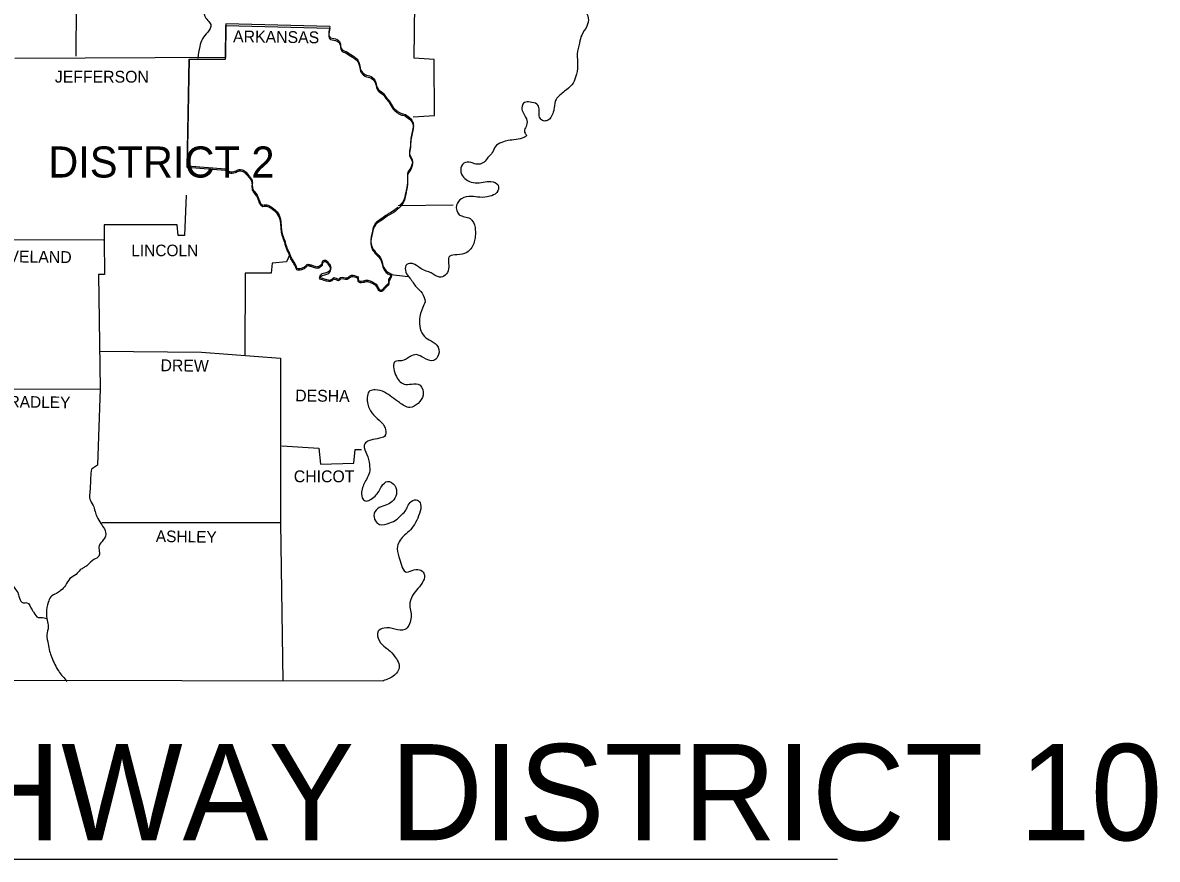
# Model space of a CAD drawing. Extents: x 191 to 3403, y 68 to 2102.
# Drawn here: x 2999.8 to 3403.5, y 1369.4 to 1667 of the extents above; entities that cross this region are included whole.
import ezdxf

# ---------------------------------------------------------------- set-up
doc = ezdxf.new("R2010")
doc.units = 0
for name, color, linetype in [('1', 7, 'Continuous'), ('2', 7, 'Continuous'), ('3', 7, 'Continuous')]:
    doc.layers.add(name, color=color, linetype=linetype)

msp = doc.modelspace()

# ---------------------------------------------------------------- linework, layer by layer
at = {"layer": '1'}
for p, q in [((3133.42, 1601.94), (3152.99, 1602.24)), ((2625.16, 1369.37), (3289.7, 1369.37))]:
    msp.add_line(p, q, dxfattribs=at)
for points in [[(3007.21, 1732.56), (3012.88, 1732.17), (3012.98, 1694.79), (3007.89, 1673.56), (3018.75, 1673.07), (3018.66, 1655.07)], [(3138.71, 1633.54), (3146.34, 1634.03), (3146.24, 1653.9), (3139.1, 1654.38), (3139.49, 1693.23), (3133.33, 1694.11), (3133.13, 1720.23), (3216.59, 1720.82)], [(3109.06, 1665.64), (3072.08, 1666.61), (3071.88, 1654.58), (2997.03, 1654.29)], [(3059.06, 1653.99), (3071.88, 1653.99), (3072.08, 1666.03), (3109.06, 1665.05)], [(3059.06, 1653.99), (3058.28, 1616.13), (3071.88, 1615.05)], [(3071.88, 1614.47), (3058.28, 1615.54), (3059.06, 1653.99)], [(3057.99, 1605.66), (3057.4, 1591.28), (3055.15, 1591.28), (3054.76, 1595.09), (3028.73, 1595.09), (3028.73, 1589.61)], [(2993.9, 1589.91), (3028.54, 1589.71)], [(3028.73, 1589.71), (3028.83, 1577.48), (3026.78, 1577.38), (3027.36, 1536.78)], [(3094.87, 1584.53), (3093.7, 1581.88), (3088.51, 1581.4), (3088.22, 1577.87), (3078.93, 1577.87), (3078.83, 1548.62)], [(3105.83, 1580.22), (3106.13, 1580.51), (3106.42, 1580.81), (3106.42, 1580.81)], [(3027.07, 1550.09), (3063.37, 1549.79), (3091.55, 1547.64)], [(3091.55, 1547.64), (3091.55, 1489.13), (3092.33, 1432.87)], [(2983.14, 1536.68), (3027.36, 1536.78)], [(3027.36, 1536.78), (3026.39, 1509.58), (3024.23, 1508.21)], [(3092.04, 1516.43), (3105.15, 1515.65), (3105.73, 1509.97), (3117.57, 1510.36), (3118.06, 1515.16), (3120.31, 1515.16)], [(2769.26, 1512.61), (2769.46, 1433.46), (3128.04, 1432.87)], [(3027.95, 1489.23), (3091.55, 1489.23)]]:
    msp.add_lwpolyline(points, dxfattribs=at)
for points in [[(3210.42, 1697.14), (3208.17, 1694.3), (3204.85, 1696.06), (3204.85, 1698.41), (3205.34, 1700.86), (3204.16, 1702.42), (3202.11, 1701.74), (3202.11, 1698.71), (3201.91, 1695.77), (3201.32, 1691.56), (3202.69, 1690.29), (3205.83, 1689.9), (3208.08, 1689.31), (3209.45, 1687.06), (3209.35, 1684.32), (3208.27, 1681.68), (3206.71, 1679.53), (3204.26, 1678.75), (3202.3, 1680.02), (3201.52, 1682.56), (3200.64, 1684.81), (3198.98, 1686.48), (3197.22, 1684.62), (3196.82, 1681.19), (3196.92, 1678.26), (3196.92, 1674.25), (3199.47, 1671.6), (3201.03, 1668.57), (3200.54, 1665.83), (3198.68, 1662.6), (3197.9, 1659.77), (3197.12, 1655.95), (3197.22, 1651.74), (3196.53, 1647.63), (3195.16, 1644.89), (3192.62, 1642.64), (3190.95, 1641.18), (3189.58, 1639.71), (3188.9, 1636.77), (3188.41, 1634.72), (3186.55, 1632.27), (3185.08, 1632.08), (3183.91, 1633.05), (3183.52, 1634.72), (3183.52, 1636.38), (3182.74, 1638.04), (3180.29, 1638.73), (3178.33, 1638.63), (3177.45, 1637.26), (3178.72, 1633.45), (3179.21, 1631), (3178.53, 1627.67), (3178.92, 1627.28), (3175.4, 1625.42), (3172.56, 1625.13), (3170.21, 1624.44), (3167.96, 1622.98), (3166.88, 1620.82), (3165.32, 1619.06), (3163.95, 1617.4), (3162.09, 1616.62), (3160.04, 1617.01), (3157.3, 1617.3), (3155.73, 1615.35), (3156.22, 1612.51), (3158.08, 1610.85), (3160.82, 1610.06), (3163.66, 1610.26), (3166.4, 1610.55), (3168.94, 1609.18), (3168.45, 1606.54), (3166, 1605.27), (3162.38, 1604.88), (3159.45, 1605.17), (3155.93, 1604.39), (3154.17, 1602.14), (3155.14, 1598.71), (3158.96, 1597.34), (3160.72, 1594.11), (3160.82, 1591.08), (3159.55, 1587.07), (3157.79, 1585.21), (3154.36, 1584.43), (3151.72, 1583.94), (3151.33, 1579.44), (3150.15, 1577.19), (3148.1, 1576.5), (3145.16, 1577.97), (3143.4, 1578.66), (3141.25, 1579.63), (3138.51, 1581.3), (3136.46, 1581), (3137.04, 1576.7), (3137.24, 1576.5), (3139.59, 1573.27), (3141.94, 1570.73), (3143.01, 1567.7)], [(3059.95, 1681.68), (3062.39, 1680.02), (3064.93, 1678.06), (3065.62, 1675.42), (3065.42, 1673.56), (3064.64, 1672), (3064.45, 1669.55), (3065.62, 1667.79), (3066.7, 1666.32), (3065.62, 1663.68), (3063.76, 1661.23), (3062.78, 1658.49), (3062.1, 1654.38)], [(3109.06, 1665.64), (3109.35, 1661.62), (3111.7, 1661.04), (3112.68, 1659.96), (3113.17, 1657.71), (3114.83, 1656.73), (3117.08, 1655.36), (3118.45, 1654.38), (3119.43, 1652.82), (3120.02, 1650.27), (3121.58, 1648.61), (3123.74, 1647.83), (3125.3, 1645.97), (3126.28, 1643.33), (3127.85, 1642.15), (3129.41, 1640.1), (3130.19, 1639.22), (3131.56, 1636.87), (3132.93, 1635.7), (3133.91, 1635.01), (3135.48, 1634.52), (3137.43, 1633.25), (3138.71, 1631.29), (3138.71, 1629.83), (3138.22, 1627.58), (3137.83, 1625.23), (3137.63, 1622.59), (3137.43, 1620.24), (3138.32, 1618.28), (3137.83, 1615.35), (3136.85, 1613.78), (3136.75, 1611.63), (3136.46, 1608.4), (3136.07, 1606.54), (3135.18, 1603.51), (3133.91, 1601.94)], [(3109.06, 1665.05), (3109.35, 1661.04), (3111.7, 1660.45), (3112.68, 1659.37), (3113.17, 1657.12), (3114.83, 1656.15), (3117.08, 1654.78), (3118.45, 1653.8), (3119.43, 1652.23), (3120.02, 1649.69), (3121.58, 1648.02), (3123.74, 1647.24), (3125.3, 1645.38), (3126.28, 1642.74), (3127.85, 1641.57), (3129.41, 1639.51), (3130.19, 1638.63), (3131.56, 1636.28), (3132.93, 1635.11), (3133.91, 1634.42), (3135.48, 1633.94), (3137.43, 1632.66), (3138.71, 1630.71), (3138.71, 1629.24), (3138.22, 1626.99), (3137.83, 1624.64), (3137.63, 1622), (3137.43, 1619.65), (3138.32, 1617.69), (3137.83, 1614.76), (3136.85, 1613.19), (3136.75, 1611.04), (3136.46, 1607.81), (3136.07, 1605.95), (3135.18, 1602.92), (3133.62, 1601.06)], [(3071.88, 1615.05), (3073.35, 1614.07), (3075.4, 1614.17), (3076.77, 1614.76), (3077.85, 1614.66), (3079.32, 1613.78), (3080.3, 1612.61), (3080.98, 1611.73), (3081.47, 1610.36), (3081.47, 1609.08), (3081.96, 1607.32), (3082.55, 1606.64), (3083.33, 1605.37), (3083.82, 1604.19), (3084.11, 1603.41), (3085.19, 1602.14), (3086.17, 1602.24), (3087.05, 1602.14), (3088.22, 1601.45), (3089.98, 1600.08), (3090.28, 1599.69), (3091.45, 1597.15), (3091.65, 1595.58), (3091.84, 1593.53), (3092.23, 1591.57), (3093.02, 1589.42), (3093.41, 1587.95), (3094.29, 1585.9), (3094.87, 1584.53), (3095.66, 1582.76), (3096.83, 1580.81), (3097.32, 1579.63), (3098.98, 1579.73), (3100.16, 1580.22), (3101.04, 1581), (3102.11, 1580.91), (3103.29, 1580.51), (3104.85, 1580.22), (3105.83, 1580.81), (3106.32, 1581.2), (3106.42, 1582.08), (3107.3, 1582.57), (3108.28, 1581.88), (3109.35, 1580.32), (3109.35, 1579.34), (3108.96, 1578.75), (3107.69, 1577.97), (3105.93, 1577.38), (3105.44, 1576.7), (3107.1, 1575.92), (3109.75, 1575.72), (3110.43, 1576.31), (3112.19, 1575.82), (3112.88, 1576.31), (3115.23, 1576.21), (3116.3, 1576.99), (3118.45, 1576.89), (3119.14, 1576.41), (3119.14, 1575.52), (3120.9, 1575.13), (3122.17, 1575.43), (3123.84, 1574.94), (3125.3, 1574.15), (3126.09, 1573.08), (3127.06, 1571.9), (3127.94, 1572.2), (3128.63, 1573.08), (3130.1, 1574.64), (3130.1, 1575.62), (3130.49, 1576.31), (3130.98, 1577.29)], [(3130.98, 1576.7), (3130.49, 1575.72), (3130.1, 1575.04), (3130.1, 1574.06), (3128.63, 1572.49), (3127.94, 1571.61), (3127.06, 1571.32), (3126.09, 1572.49), (3125.3, 1573.57), (3123.84, 1574.35), (3122.17, 1574.84), (3120.9, 1574.55), (3119.14, 1574.94), (3119.14, 1575.82), (3118.45, 1576.31), (3116.3, 1576.41), (3115.23, 1575.62), (3112.88, 1575.72), (3112.19, 1575.23), (3110.43, 1575.72), (3109.75, 1575.13), (3107.1, 1575.33), (3105.44, 1576.11), (3105.93, 1576.8), (3107.69, 1577.38), (3108.96, 1578.17), (3109.35, 1578.75), (3109.35, 1579.73), (3108.28, 1581.3), (3107.3, 1581.98), (3106.42, 1581.49), (3106.32, 1580.61), (3105.83, 1580.22), (3104.85, 1579.63), (3103.29, 1579.93), (3102.11, 1580.32), (3101.04, 1580.42), (3100.16, 1579.63), (3098.98, 1579.14), (3097.32, 1579.05), (3096.83, 1580.22), (3095.66, 1582.18), (3094.87, 1583.94), (3094.29, 1585.31), (3093.41, 1587.36), (3093.02, 1588.83), (3092.23, 1590.98), (3091.84, 1592.94), (3091.65, 1594.99), (3091.45, 1596.56), (3090.28, 1599.1), (3089.98, 1599.5), (3088.22, 1600.87), (3087.05, 1601.55), (3086.17, 1601.65), (3085.19, 1601.55), (3084.11, 1602.82), (3083.82, 1603.6), (3083.33, 1604.78), (3082.55, 1606.05), (3081.96, 1606.74), (3081.47, 1608.5), (3081.47, 1609.77), (3080.98, 1611.14), (3080.3, 1612.02), (3079.32, 1613.19), (3077.85, 1614.07), (3076.77, 1614.17), (3075.4, 1613.58), (3073.35, 1613.49), (3071.88, 1614.47)], [(3133.23, 1601.35), (3131.17, 1599.69), (3129.41, 1598.71), (3127.55, 1597.34), (3125.3, 1595.68), (3124.23, 1592.84), (3123.64, 1588.93), (3124.42, 1586.58), (3126.18, 1584.53), (3127.36, 1582.86), (3128.24, 1579.93), (3130.39, 1577.87), (3131.08, 1577.58)], [(3133.62, 1601.06), (3131.17, 1599.1), (3129.41, 1598.13), (3127.55, 1596.76), (3125.3, 1595.09), (3124.23, 1592.26), (3123.64, 1588.34), (3124.42, 1585.99), (3126.18, 1583.94), (3127.36, 1582.28), (3128.24, 1579.34), (3130.39, 1577.29), (3131.08, 1576.99)], [(3143.01, 1567.7), (3142.03, 1565.45), (3140.96, 1561.53), (3141.25, 1558.21), (3142.72, 1555.37), (3145.07, 1553.8), (3147.61, 1551.55), (3147.41, 1548.13), (3145.95, 1546.86), (3142.52, 1547.74), (3139.88, 1548.91), (3137.63, 1548.23), (3134.6, 1546.76), (3132.35, 1546.47), (3132.45, 1541.77), (3135.48, 1538.44), (3138.12, 1538.44), (3141.15, 1538.05), (3142.23, 1534.53), (3140.47, 1531.59), (3137.53, 1530.13), (3133.81, 1531.89), (3131.17, 1533.75), (3128.53, 1535.51), (3125.2, 1536.39), (3123.35, 1536), (3122.47, 1531.89), (3124.03, 1528.17), (3126.57, 1525.63), (3128.92, 1522.3), (3128.53, 1519.85), (3126.77, 1519.17), (3123.64, 1518.48), (3121.78, 1517.51), (3121.29, 1516.72), (3122.27, 1513.4), (3123.15, 1509.78), (3123.15, 1507.04), (3122.07, 1504.49), (3120.41, 1500.58), (3120.61, 1498.03), (3121.78, 1496.86), (3123.25, 1497.25), (3125.2, 1498.62), (3126.48, 1500.19), (3127.55, 1502.14), (3129.61, 1503.81), (3132.15, 1502.34), (3132.74, 1499.31), (3131.27, 1496.67), (3129.22, 1495.49), (3126.67, 1494.51), (3124.81, 1492.36), (3125.3, 1489.82), (3126.77, 1488.45), (3130.39, 1489.13), (3132.84, 1490.21), (3134.21, 1491.58), (3135.87, 1493.24), (3136.75, 1494.9), (3138.02, 1496.67), (3140.27, 1497.15), (3141.35, 1495.69), (3140.96, 1492.36), (3139.59, 1489.23), (3137.73, 1486.59), (3135.67, 1484.73), (3133.13, 1480.72), (3133.62, 1477), (3134.6, 1473.97), (3135.97, 1471.62), (3138.32, 1472.11), (3140.96, 1472.4), (3142.52, 1471.13), (3142.33, 1468.39), (3140.37, 1465.75), (3138.51, 1463.2), (3137.53, 1459.68), (3137.92, 1457.24), (3137.92, 1454.98), (3137.14, 1452.54), (3135.77, 1451.17), (3132.15, 1451.27), (3128.34, 1451.66), (3126.28, 1450.48), (3126.67, 1447.16), (3128.92, 1444.71), (3130.49, 1443.44), (3132.74, 1440.7), (3133.72, 1438.45), (3133.42, 1436.49), (3132.05, 1434.83), (3128.04, 1432.87)], [(3024.23, 1508.21), (3023.94, 1505.18), (3023.84, 1502.34), (3023.65, 1499.6), (3023.65, 1497.55), (3024.82, 1495.3), (3025.51, 1493.14), (3026.19, 1491.28), (3027.56, 1488.84), (3028.83, 1486.98), (3029.22, 1484.34), (3028.44, 1482.97), (3026.97, 1480.91), (3026.87, 1477.19), (3025.11, 1476.02), (3022.86, 1474.06), (3021.59, 1473.18), (3020.22, 1472.3), (3018.75, 1470.74), (3016.6, 1469.27), (3015.04, 1466.82), (3013.28, 1464.96), (3011.81, 1463.99), (3009.75, 1462.71), (3008.87, 1460.76), (3008.19, 1457.14), (3008.48, 1454.5), (3008.87, 1452.15), (3008.38, 1449.21), (3008.87, 1445.98), (3009.36, 1443.44), (3010.14, 1441.19), (3011.22, 1438.65), (3012.59, 1436.3), (3015.53, 1432.68)], [(2926.69, 1485.61), (2928.25, 1486.69), (2929.72, 1487.27), (2931.19, 1486.98), (2932.75, 1486.78), (2934.12, 1486.98), (2935.88, 1486.69), (2937.35, 1485.8), (2939.01, 1485.12), (2940.68, 1485.12), (2942.14, 1485.12), (2943.42, 1484.24), (2945.77, 1484.34), (2947.72, 1485.12), (2949.68, 1485.71), (2952.32, 1486), (2954.67, 1484.34), (2956.33, 1482.97), (2957.7, 1481.4), (2958.68, 1479.64), (2959.76, 1478.66), (2961.52, 1477.98), (2962.89, 1477.68), (2964.55, 1477.19), (2965.43, 1476.8), (2966.21, 1474.94), (2967.49, 1472.4), (2969.93, 1471.52), (2972.96, 1472.69), (2975.41, 1473.38), (2977.17, 1473.97), (2978.25, 1474.36), (2979.23, 1474.46), (2978.93, 1474.65), (2980.11, 1474.94), (2981.18, 1474.16), (2981.87, 1473.09), (2983.04, 1471.52), (2984.12, 1470.15), (2985.19, 1469.66), (2986.27, 1470.25), (2987.74, 1469.76), (2989.01, 1469.27), (2990.48, 1468.88), (2991.75, 1468.78), (2993.41, 1468.39), (2994.69, 1467.7), (2995.86, 1467.02), (2997.03, 1465.75), (2998.21, 1463.79), (2998.6, 1462.23), (2999.97, 1460.66), (3001.24, 1460.66), (3003.1, 1458.12), (3003.78, 1457.14), (3005.25, 1455.38), (3006.33, 1455.38), (3008.38, 1454.98)]]:
    msp.add_spline(points, degree=3, dxfattribs=at)
at = {"layer": '3'}
msp.add_line((3130.78, 1577.48), (3136.95, 1576.7), dxfattribs=at)

# ---------------------------------------------------------------- texts
at = {"layer": '2'}
for s, height, rotation, p in [('ARKANSAS', 4.206, 359.2678, (3074.62, 1660.06)), ('CLEVELAND', 4.207, 359.3377, (2983.73, 1581.88)), ('DREW', 4.206, 359.2258, (3048.79, 1543.04)), ('BRADLEY', 4.108, 359.1449, (2991.07, 1530.22)), ('DESHA', 4.206, 359.3704, (3096.73, 1532.28)), ('ASHLEY', 4.109, 359.2361, (3047.13, 1482.28))]:
    msp.add_text(s, height=height, rotation=rotation, dxfattribs=at).set_placement(p)
for s, height, p in [('JEFFERSON', 4.207, (3011.22, 1645.68)), ('LINCOLN', 4.109, (3038.42, 1583.94)), ('CHICOT', 4.207, (3096.24, 1503.51)), ('ARKANSAS HIGHWAY DISTRICT 10', 34.244, (2636.86, 1376.13))]:
    msp.add_text(s, height=height, dxfattribs=at).set_placement(p)
at = {"layer": '3'}
msp.add_text('DISTRICT 2', height=11.056, dxfattribs=at).set_placement((3008.87, 1611.92))

doc.saveas('drawing.dxf')
